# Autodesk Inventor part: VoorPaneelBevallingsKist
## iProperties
Created: 2010-03
Part Number: VoorPaneelBevallingsKist
Document SubType Name: Modeling
Designer: Ferry
Density: 1 g/cm^3
Author: Ferry
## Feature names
1. Extrusion1
